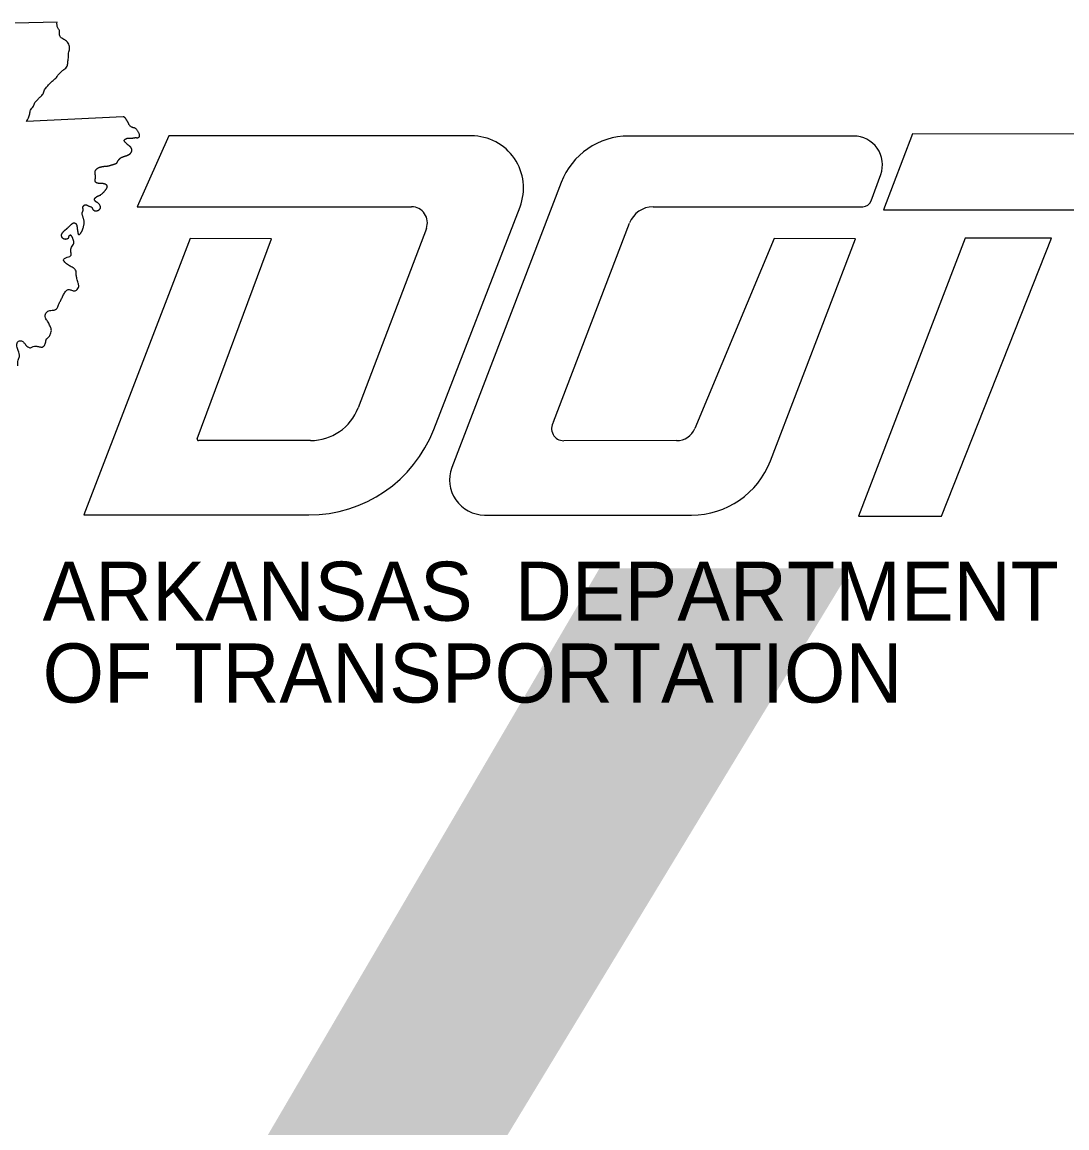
# Model space of a CAD drawing. Extents: x 1373878 to 1386598, y 1168333 to 1170533.
# Drawn here: x 1375442.6 to 1375493.8, y 1170196.3 to 1170250.5 of the extents above; entities that cross this region are included whole.
import ezdxf

# ---------------------------------------------------------------- set-up
doc = ezdxf.new("R2010")
doc.units = 0
doc.layers.add('1', color=7, linetype='Continuous')
doc.layers.add('R_Draft', color=7, linetype='Continuous')

msp = doc.modelspace()

# ---------------------------------------------------------------- linework, layer by layer
at = {"layer": '1'}
for p, q in [((1375447.561, 1170245.888), (1375442.814, 1170245.65)), ((1375449.8, 1170244.947), (1375448.241, 1170241.475)), ((1375464.634, 1170244.953), (1375449.8, 1170244.947)), ((1375483.381, 1170244.945), (1375472.342, 1170244.942)), ((1375486.266, 1170245.051), (1375484.847, 1170241.332)), ((1375503.446, 1170245.021), (1375486.266, 1170245.051)), ((1375484.236, 1170241.763), (1375484.706, 1170243.053)), ((1375469.04, 1170242.671), (1375463.68, 1170228.688)), ((1375448.241, 1170241.475), (1375461.698, 1170241.474)), ((1375462.79, 1170230.561), (1375467.02, 1170241.472)), ((1375473.546, 1170241.473), (1375483.827, 1170241.477)), ((1375484.847, 1170241.332), (1375501.324, 1170241.332)), ((1375468.667, 1170230.931), (1375472.394, 1170240.68)), ((1375462.428, 1170240.415), (1375459.082, 1170231.62)), ((1375454.839, 1170239.912), (1375450.847, 1170239.914)), ((1375451.196, 1170230.092), (1375454.839, 1170239.912)), ((1375479.485, 1170239.917), (1375475.598, 1170230.611)), ((1375479.303, 1170229.025), (1375483.476, 1170239.905)), ((1375483.476, 1170239.905), (1375479.485, 1170239.917)), ((1375488.854, 1170239.937), (1375483.624, 1170226.301)), ((1375487.68, 1170226.301), (1375493.076, 1170239.937)), ((1375493.076, 1170239.937), (1375488.854, 1170239.937)), ((1375456.751, 1170230.014), (1375451.251, 1170230.013)), ((1375474.7, 1170230.012), (1375469.166, 1170230.006)), ((1375465.277, 1170226.364), (1375475.427, 1170226.361)), ((1375483.624, 1170226.301), (1375487.68, 1170226.301))]:
    msp.add_line(p, q, dxfattribs=at)
for points in [[(1375444.317, 1170250.528), (1375439.463, 1170250.415), (1375428.999, 1170250.255), (1375420.123, 1170250.237), (1375410.017, 1170250.244)], [(1375450.847, 1170239.914), (1375445.637, 1170226.376), (1375456.659, 1170226.366)]]:
    msp.add_lwpolyline(points, dxfattribs=at)
for centre, radius, start, end in [((1375464.635, 1170242.396), 2.557, 338.81, 90.0244), ((1375472.343, 1170241.404), 3.538, 90.0159, 159.0252), ((1375483.381, 1170243.535), 1.41, 339.9797, 90.0159), ((1375483.827, 1170241.912), 0.435, 270.0183, 339.9797), ((1375461.698, 1170240.693), 0.781, 339.1692, 89.9954), ((1375473.547, 1170240.24), 1.234, 90.0183, 159.0781), ((1375456.751, 1170232.507), 2.494, 270.0081, 339.1692), ((1375469.164, 1170230.602), 0.596, 146.4856, 270.228), ((1375456.665, 1170232.935), 6.569, 269.9471, 338.81), ((1375474.699, 1170230.987), 0.975, 270.0618, 337.3322), ((1375451.251, 1170230.072), 0.0589, 159.6445, 270.0081), ((1375465.278, 1170228.076), 1.711, 159.0252, 269.9823), ((1375475.428, 1170230.511), 4.15, 269.9823, 339.0187)]:
    msp.add_arc(centre, radius, start, end, dxfattribs=at)
for points in [[(1375442.814, 1170245.65), (1375442.981, 1170246.03), (1375443.016, 1170246.218), (1375443.158, 1170246.407), (1375443.233, 1170246.581), (1375443.386, 1170246.748), (1375443.5, 1170246.872), (1375443.638, 1170247.011), (1375443.706, 1170247.203), (1375443.834, 1170247.377), (1375443.965, 1170247.515), (1375444.125, 1170247.672), (1375444.292, 1170247.821), (1375444.384, 1170247.963), (1375444.516, 1170248.094), (1375444.658, 1170248.205), (1375444.811, 1170248.361), (1375444.846, 1170248.556), (1375444.871, 1170248.77), (1375444.882, 1170249.011), (1375444.931, 1170249.228), (1375444.896, 1170249.441), (1375444.736, 1170249.626), (1375444.555, 1170249.736), (1375444.448, 1170249.85), (1375444.434, 1170250.113), (1375444.349, 1170250.255), (1375444.317, 1170250.528)], [(1375444.089, 1170236.404), (1375444.239, 1170236.433), (1375444.377, 1170236.621), (1375444.445, 1170236.781), (1375444.516, 1170236.93), (1375444.608, 1170237.108), (1375444.701, 1170237.278), (1375444.832, 1170237.406), (1375444.995, 1170237.396), (1375445.138, 1170237.349), (1375445.269, 1170237.389), (1375445.379, 1170237.573), (1375445.354, 1170237.733), (1375445.294, 1170237.954), (1375445.262, 1170238.121), (1375445.226, 1170238.373), (1375445.109, 1170238.483), (1375444.921, 1170238.586), (1375444.736, 1170238.728), (1375444.633, 1170238.874), (1375444.811, 1170239.002), (1375445.01, 1170239.108), (1375444.988, 1170239.304), (1375445.027, 1170239.496), (1375445.138, 1170239.691), (1375445.113, 1170239.869)], [(1375442.394, 1170233.672), (1375442.416, 1170233.963), (1375442.473, 1170234.134), (1375442.412, 1170234.422), (1375442.352, 1170234.635), (1375442.377, 1170234.841), (1375442.508, 1170234.908), (1375442.636, 1170234.866), (1375442.746, 1170234.752), (1375442.881, 1170234.606), (1375443.013, 1170234.56), (1375443.148, 1170234.631), (1375443.286, 1170234.642), (1375443.446, 1170234.613), (1375443.595, 1170234.599), (1375443.674, 1170234.649), (1375443.752, 1170234.798), (1375443.805, 1170234.997), (1375443.915, 1170235.093), (1375444.001, 1170235.25), (1375444.036, 1170235.459), (1375443.972, 1170235.63), (1375443.883, 1170235.822), (1375443.77, 1170235.981), (1375443.752, 1170236.212), (1375443.869, 1170236.351), (1375444.072, 1170236.401), (1375444.089, 1170236.404)]]:
    msp.add_spline(points, degree=3, dxfattribs=at)
for points in [[(1375447.904, 1170244.833), (1375447.919, 1170244.831), (1375447.934, 1170244.83), (1375447.948, 1170244.833), (1375447.98, 1170244.838), (1375448.012, 1170244.843), (1375448.044, 1170244.848), (1375448.076, 1170244.854), (1375448.108, 1170244.859), (1375448.14, 1170244.865), (1375448.147, 1170244.866), (1375448.155, 1170244.866), (1375448.162, 1170244.866), (1375448.17, 1170244.866), (1375448.177, 1170244.866), (1375448.184, 1170244.865), (1375448.199, 1170244.864), (1375448.214, 1170244.863), (1375448.229, 1170244.861), (1375448.244, 1170244.86), (1375448.259, 1170244.861), (1375448.273, 1170244.863), (1375448.289, 1170244.865), (1375448.304, 1170244.871), (1375448.318, 1170244.879), (1375448.321, 1170244.881), (1375448.323, 1170244.882), (1375448.326, 1170244.885), (1375448.329, 1170244.887), (1375448.331, 1170244.889), (1375448.333, 1170244.891), (1375448.338, 1170244.896), (1375448.342, 1170244.9), (1375448.346, 1170244.906), (1375448.353, 1170244.917), (1375448.358, 1170244.928), (1375448.361, 1170244.941), (1375448.365, 1170244.954), (1375448.366, 1170244.966), (1375448.366, 1170244.979), (1375448.365, 1170244.99), (1375448.364, 1170245.002), (1375448.36, 1170245.014), (1375448.342, 1170245.072), (1375448.315, 1170245.122), (1375448.282, 1170245.174), (1375448.248, 1170245.228), (1375448.212, 1170245.276), (1375448.161, 1170245.316), (1375448.15, 1170245.325), (1375448.138, 1170245.331), (1375448.124, 1170245.335), (1375448.11, 1170245.339), (1375448.096, 1170245.342), (1375448.083, 1170245.345), (1375448.069, 1170245.348), (1375448.054, 1170245.35), (1375448.041, 1170245.354), (1375448.027, 1170245.357), (1375448.014, 1170245.362), (1375448.001, 1170245.369), (1375447.951, 1170245.397), (1375447.906, 1170245.431), (1375447.87, 1170245.476), (1375447.859, 1170245.49), (1375447.849, 1170245.505), (1375447.841, 1170245.521), (1375447.833, 1170245.537), (1375447.826, 1170245.553), (1375447.819, 1170245.569), (1375447.811, 1170245.585), (1375447.805, 1170245.601), (1375447.797, 1170245.617), (1375447.789, 1170245.633), (1375447.78, 1170245.649), (1375447.771, 1170245.664), (1375447.763, 1170245.675), (1375447.756, 1170245.687), (1375447.749, 1170245.698), (1375447.742, 1170245.71), (1375447.735, 1170245.722), (1375447.727, 1170245.734), (1375447.713, 1170245.757), (1375447.697, 1170245.78), (1375447.682, 1170245.803), (1375447.667, 1170245.825), (1375447.65, 1170245.843), (1375447.628, 1170245.859), (1375447.608, 1170245.874), (1375447.585, 1170245.885), (1375447.561, 1170245.888)], [(1375447.341, 1170243.778), (1375447.344, 1170243.781), (1375447.347, 1170243.785), (1375447.351, 1170243.788), (1375447.364, 1170243.803), (1375447.377, 1170243.817), (1375447.39, 1170243.83), (1375447.404, 1170243.844), (1375447.418, 1170243.857), (1375447.434, 1170243.868), (1375447.449, 1170243.88), (1375447.465, 1170243.89), (1375447.483, 1170243.898), (1375447.499, 1170243.906), (1375447.515, 1170243.913), (1375447.532, 1170243.918), (1375447.548, 1170243.924), (1375447.565, 1170243.93), (1375447.582, 1170243.935), (1375447.599, 1170243.941), (1375447.615, 1170243.946), (1375447.632, 1170243.951), (1375447.649, 1170243.957), (1375447.665, 1170243.963), (1375447.682, 1170243.969), (1375447.715, 1170243.981), (1375447.748, 1170243.994), (1375447.78, 1170244.008), (1375447.814, 1170244.021), (1375447.846, 1170244.039), (1375447.877, 1170244.058), (1375447.892, 1170244.067), (1375447.904, 1170244.079), (1375447.916, 1170244.091), (1375447.928, 1170244.104), (1375447.937, 1170244.117), (1375447.946, 1170244.132), (1375447.962, 1170244.161), (1375447.974, 1170244.19), (1375447.98, 1170244.221), (1375447.983, 1170244.236), (1375447.984, 1170244.25), (1375447.983, 1170244.264), (1375447.981, 1170244.279), (1375447.979, 1170244.294), (1375447.975, 1170244.309), (1375447.97, 1170244.324), (1375447.965, 1170244.339), (1375447.957, 1170244.353), (1375447.949, 1170244.367), (1375447.941, 1170244.38), (1375447.93, 1170244.392), (1375447.917, 1170244.408), (1375447.903, 1170244.422), (1375447.887, 1170244.435), (1375447.872, 1170244.448), (1375447.856, 1170244.46), (1375447.841, 1170244.472), (1375447.825, 1170244.484), (1375447.809, 1170244.496), (1375447.794, 1170244.508), (1375447.779, 1170244.521), (1375447.764, 1170244.535), (1375447.749, 1170244.548), (1375447.72, 1170244.575), (1375447.692, 1170244.603), (1375447.664, 1170244.631), (1375447.651, 1170244.644), (1375447.64, 1170244.659), (1375447.629, 1170244.674), (1375447.62, 1170244.687), (1375447.614, 1170244.7), (1375447.611, 1170244.715), (1375447.61, 1170244.718), (1375447.61, 1170244.722), (1375447.61, 1170244.725), (1375447.61, 1170244.728), (1375447.611, 1170244.731), (1375447.612, 1170244.734), (1375447.614, 1170244.741), (1375447.617, 1170244.747), (1375447.621, 1170244.752), (1375447.632, 1170244.766), (1375447.644, 1170244.777), (1375447.659, 1170244.787), (1375447.676, 1170244.798), (1375447.692, 1170244.808), (1375447.711, 1170244.817), (1375447.728, 1170244.826), (1375447.745, 1170244.833), (1375447.763, 1170244.84), (1375447.771, 1170244.842), (1375447.779, 1170244.844), (1375447.787, 1170244.845), (1375447.794, 1170244.847), (1375447.802, 1170244.847), (1375447.81, 1170244.847), (1375447.825, 1170244.845), (1375447.841, 1170244.843), (1375447.856, 1170244.841), (1375447.872, 1170244.839), (1375447.887, 1170244.835), (1375447.902, 1170244.833), (1375447.903, 1170244.833), (1375447.903, 1170244.833), (1375447.904, 1170244.833)], [(1375446.185, 1170242.779), (1375446.186, 1170242.792), (1375446.187, 1170242.805), (1375446.189, 1170242.818), (1375446.193, 1170242.838), (1375446.199, 1170242.858), (1375446.202, 1170242.878), (1375446.205, 1170242.898), (1375446.208, 1170242.919), (1375446.207, 1170242.939), (1375446.206, 1170242.958), (1375446.204, 1170242.977), (1375446.201, 1170242.996), (1375446.198, 1170243.016), (1375446.195, 1170243.035), (1375446.193, 1170243.054), (1375446.19, 1170243.073), (1375446.187, 1170243.093), (1375446.185, 1170243.112), (1375446.183, 1170243.131), (1375446.182, 1170243.15), (1375446.182, 1170243.17), (1375446.182, 1170243.185), (1375446.185, 1170243.199), (1375446.188, 1170243.214), (1375446.191, 1170243.229), (1375446.196, 1170243.243), (1375446.204, 1170243.257), (1375446.221, 1170243.286), (1375446.24, 1170243.311), (1375446.264, 1170243.333), (1375446.271, 1170243.34), (1375446.279, 1170243.347), (1375446.287, 1170243.353), (1375446.295, 1170243.359), (1375446.303, 1170243.364), (1375446.311, 1170243.37), (1375446.327, 1170243.38), (1375446.343, 1170243.389), (1375446.36, 1170243.396), (1375446.376, 1170243.404), (1375446.393, 1170243.41), (1375446.41, 1170243.415), (1375446.428, 1170243.42), (1375446.445, 1170243.425), (1375446.463, 1170243.429), (1375446.495, 1170243.436), (1375446.528, 1170243.443), (1375446.56, 1170243.449), (1375446.593, 1170243.455), (1375446.626, 1170243.46), (1375446.658, 1170243.465), (1375446.673, 1170243.466), (1375446.688, 1170243.468), (1375446.703, 1170243.469), (1375446.718, 1170243.47), (1375446.733, 1170243.471), (1375446.747, 1170243.472), (1375446.762, 1170243.473), (1375446.777, 1170243.474), (1375446.792, 1170243.475), (1375446.807, 1170243.477), (1375446.821, 1170243.479), (1375446.836, 1170243.482), (1375446.87, 1170243.49), (1375446.903, 1170243.499), (1375446.936, 1170243.509), (1375446.969, 1170243.519), (1375447.002, 1170243.529), (1375447.035, 1170243.539), (1375447.067, 1170243.549), (1375447.1, 1170243.558), (1375447.132, 1170243.568), (1375447.164, 1170243.578), (1375447.196, 1170243.589), (1375447.227, 1170243.603), (1375447.239, 1170243.609), (1375447.25, 1170243.618), (1375447.257, 1170243.629), (1375447.264, 1170243.642), (1375447.269, 1170243.654), (1375447.275, 1170243.667), (1375447.28, 1170243.681), (1375447.284, 1170243.695), (1375447.29, 1170243.709), (1375447.296, 1170243.722), (1375447.303, 1170243.734), (1375447.312, 1170243.745), (1375447.322, 1170243.756), (1375447.331, 1170243.767), (1375447.341, 1170243.778)], [(1375446.217, 1170241.725), (1375446.214, 1170241.728), (1375446.21, 1170241.731), (1375446.207, 1170241.734), (1375446.187, 1170241.753), (1375446.173, 1170241.775), (1375446.161, 1170241.799), (1375446.151, 1170241.82), (1375446.147, 1170241.846), (1375446.157, 1170241.866), (1375446.165, 1170241.879), (1375446.174, 1170241.891), (1375446.185, 1170241.903), (1375446.197, 1170241.915), (1375446.208, 1170241.927), (1375446.221, 1170241.937), (1375446.248, 1170241.96), (1375446.276, 1170241.98), (1375446.307, 1170241.997), (1375446.319, 1170242.004), (1375446.332, 1170242.011), (1375446.346, 1170242.016), (1375446.359, 1170242.02), (1375446.373, 1170242.025), (1375446.386, 1170242.03), (1375446.4, 1170242.034), (1375446.413, 1170242.039), (1375446.426, 1170242.044), (1375446.439, 1170242.049), (1375446.451, 1170242.056), (1375446.463, 1170242.065), (1375446.519, 1170242.106), (1375446.569, 1170242.153), (1375446.616, 1170242.203), (1375446.628, 1170242.217), (1375446.64, 1170242.23), (1375446.652, 1170242.244), (1375446.663, 1170242.258), (1375446.674, 1170242.272), (1375446.685, 1170242.286), (1375446.707, 1170242.314), (1375446.727, 1170242.344), (1375446.747, 1170242.374), (1375446.761, 1170242.395), (1375446.771, 1170242.419), (1375446.779, 1170242.443), (1375446.783, 1170242.455), (1375446.784, 1170242.468), (1375446.782, 1170242.48), (1375446.78, 1170242.491), (1375446.776, 1170242.502), (1375446.769, 1170242.512), (1375446.763, 1170242.52), (1375446.757, 1170242.526), (1375446.751, 1170242.532), (1375446.744, 1170242.538), (1375446.738, 1170242.544), (1375446.731, 1170242.549), (1375446.718, 1170242.559), (1375446.703, 1170242.568), (1375446.688, 1170242.576), (1375446.657, 1170242.591), (1375446.625, 1170242.602), (1375446.591, 1170242.608), (1375446.576, 1170242.611), (1375446.561, 1170242.613), (1375446.546, 1170242.613), (1375446.531, 1170242.613), (1375446.515, 1170242.613), (1375446.5, 1170242.613), (1375446.485, 1170242.612), (1375446.47, 1170242.612), (1375446.455, 1170242.612), (1375446.44, 1170242.612), (1375446.425, 1170242.614), (1375446.41, 1170242.615), (1375446.391, 1170242.618), (1375446.372, 1170242.62), (1375446.353, 1170242.623), (1375446.333, 1170242.626), (1375446.314, 1170242.63), (1375446.295, 1170242.634), (1375446.277, 1170242.637), (1375446.26, 1170242.645), (1375446.244, 1170242.655), (1375446.227, 1170242.666), (1375446.214, 1170242.68), (1375446.204, 1170242.697), (1375446.201, 1170242.702), (1375446.198, 1170242.707), (1375446.196, 1170242.712), (1375446.194, 1170242.717), (1375446.192, 1170242.722), (1375446.19, 1170242.727), (1375446.187, 1170242.737), (1375446.185, 1170242.747), (1375446.185, 1170242.757), (1375446.185, 1170242.764), (1375446.185, 1170242.772), (1375446.185, 1170242.779)], [(1375445.546, 1170241.148), (1375445.547, 1170241.155), (1375445.548, 1170241.162), (1375445.549, 1170241.168), (1375445.553, 1170241.185), (1375445.558, 1170241.201), (1375445.565, 1170241.217), (1375445.571, 1170241.234), (1375445.579, 1170241.249), (1375445.585, 1170241.266), (1375445.591, 1170241.282), (1375445.596, 1170241.298), (1375445.599, 1170241.315), (1375445.601, 1170241.322), (1375445.601, 1170241.329), (1375445.6, 1170241.337), (1375445.6, 1170241.344), (1375445.599, 1170241.351), (1375445.598, 1170241.359), (1375445.595, 1170241.374), (1375445.591, 1170241.388), (1375445.588, 1170241.403), (1375445.585, 1170241.418), (1375445.583, 1170241.433), (1375445.584, 1170241.448), (1375445.584, 1170241.464), (1375445.591, 1170241.479), (1375445.599, 1170241.493), (1375445.604, 1170241.499), (1375445.609, 1170241.505), (1375445.614, 1170241.512), (1375445.619, 1170241.518), (1375445.624, 1170241.524), (1375445.629, 1170241.53), (1375445.639, 1170241.541), (1375445.65, 1170241.55), (1375445.663, 1170241.56), (1375445.673, 1170241.568), (1375445.686, 1170241.573), (1375445.698, 1170241.576), (1375445.71, 1170241.579), (1375445.723, 1170241.579), (1375445.735, 1170241.574), (1375445.775, 1170241.558), (1375445.815, 1170241.538), (1375445.855, 1170241.521), (1375445.9, 1170241.502), (1375445.946, 1170241.487), (1375445.99, 1170241.468), (1375446.005, 1170241.461), (1375446.018, 1170241.451), (1375446.026, 1170241.438), (1375446.035, 1170241.423), (1375446.042, 1170241.409), (1375446.05, 1170241.394), (1375446.058, 1170241.379), (1375446.065, 1170241.363), (1375446.074, 1170241.348), (1375446.082, 1170241.333), (1375446.093, 1170241.322), (1375446.108, 1170241.311), (1375446.133, 1170241.293), (1375446.161, 1170241.284), (1375446.19, 1170241.279), (1375446.218, 1170241.274), (1375446.247, 1170241.273), (1375446.275, 1170241.279), (1375446.302, 1170241.286), (1375446.329, 1170241.295), (1375446.354, 1170241.31), (1375446.367, 1170241.318), (1375446.379, 1170241.327), (1375446.391, 1170241.337), (1375446.397, 1170241.342), (1375446.402, 1170241.347), (1375446.408, 1170241.353), (1375446.414, 1170241.359), (1375446.419, 1170241.365), (1375446.424, 1170241.372), (1375446.45, 1170241.408), (1375446.45, 1170241.463), (1375446.435, 1170241.503), (1375446.414, 1170241.555), (1375446.384, 1170241.604), (1375446.342, 1170241.645), (1375446.332, 1170241.655), (1375446.322, 1170241.664), (1375446.31, 1170241.671), (1375446.299, 1170241.677), (1375446.287, 1170241.684), (1375446.275, 1170241.69), (1375446.263, 1170241.696), (1375446.251, 1170241.703), (1375446.24, 1170241.709), (1375446.231, 1170241.713), (1375446.224, 1170241.719), (1375446.217, 1170241.725)], [(1375445.15, 1170240.69), (1375445.153, 1170240.69), (1375445.157, 1170240.69), (1375445.16, 1170240.69), (1375445.178, 1170240.688), (1375445.196, 1170240.68), (1375445.212, 1170240.668), (1375445.223, 1170240.66), (1375445.231, 1170240.652), (1375445.239, 1170240.643), (1375445.247, 1170240.634), (1375445.254, 1170240.626), (1375445.261, 1170240.616), (1375445.267, 1170240.607), (1375445.273, 1170240.597), (1375445.277, 1170240.587), (1375445.281, 1170240.576), (1375445.285, 1170240.566), (1375445.287, 1170240.554), (1375445.29, 1170240.539), (1375445.293, 1170240.523), (1375445.294, 1170240.507), (1375445.296, 1170240.491), (1375445.298, 1170240.475), (1375445.3, 1170240.459), (1375445.304, 1170240.427), (1375445.308, 1170240.395), (1375445.312, 1170240.363), (1375445.317, 1170240.322), (1375445.325, 1170240.282), (1375445.332, 1170240.242), (1375445.339, 1170240.202), (1375445.349, 1170240.164), (1375445.361, 1170240.125), (1375445.363, 1170240.12), (1375445.365, 1170240.116), (1375445.37, 1170240.113), (1375445.374, 1170240.11), (1375445.379, 1170240.11), (1375445.383, 1170240.111), (1375445.396, 1170240.113), (1375445.408, 1170240.118), (1375445.419, 1170240.126), (1375445.446, 1170240.146), (1375445.469, 1170240.166), (1375445.486, 1170240.192), (1375445.497, 1170240.21), (1375445.508, 1170240.227), (1375445.518, 1170240.246), (1375445.528, 1170240.263), (1375445.538, 1170240.281), (1375445.547, 1170240.299), (1375445.556, 1170240.317), (1375445.564, 1170240.336), (1375445.572, 1170240.355), (1375445.58, 1170240.374), (1375445.586, 1170240.393), (1375445.592, 1170240.412), (1375445.615, 1170240.484), (1375445.63, 1170240.556), (1375445.642, 1170240.629), (1375445.651, 1170240.678), (1375445.658, 1170240.73), (1375445.646, 1170240.778), (1375445.629, 1170240.844), (1375445.611, 1170240.909), (1375445.592, 1170240.974), (1375445.579, 1170241.022), (1375445.563, 1170241.071), (1375445.55, 1170241.119), (1375445.547, 1170241.129), (1375445.546, 1170241.138), (1375445.546, 1170241.148)], [(1375445.113, 1170239.869), (1375445.1, 1170239.904), (1375445.088, 1170239.939), (1375445.07, 1170239.973), (1375445.062, 1170239.989), (1375445.053, 1170240.005), (1375445.043, 1170240.02), (1375445.038, 1170240.028), (1375445.032, 1170240.035), (1375445.027, 1170240.043), (1375445.021, 1170240.05), (1375445.016, 1170240.057), (1375445.01, 1170240.064), (1375445.004, 1170240.071), (1375444.995, 1170240.075), (1375444.987, 1170240.076), (1375444.977, 1170240.078), (1375444.967, 1170240.077), (1375444.957, 1170240.074), (1375444.947, 1170240.071), (1375444.937, 1170240.068), (1375444.927, 1170240.063), (1375444.918, 1170240.058), (1375444.91, 1170240.054), (1375444.903, 1170240.046), (1375444.895, 1170240.038), (1375444.89, 1170240.028), (1375444.887, 1170240.018), (1375444.885, 1170240.006), (1375444.883, 1170239.994), (1375444.881, 1170239.982), (1375444.878, 1170239.97), (1375444.876, 1170239.958), (1375444.872, 1170239.946), (1375444.868, 1170239.935), (1375444.86, 1170239.926), (1375444.85, 1170239.918), (1375444.841, 1170239.912), (1375444.832, 1170239.907), (1375444.823, 1170239.903), (1375444.814, 1170239.898), (1375444.806, 1170239.894), (1375444.797, 1170239.89), (1375444.788, 1170239.887), (1375444.779, 1170239.884), (1375444.77, 1170239.882), (1375444.761, 1170239.881), (1375444.752, 1170239.88), (1375444.743, 1170239.879), (1375444.732, 1170239.879), (1375444.72, 1170239.88), (1375444.709, 1170239.881), (1375444.697, 1170239.882), (1375444.685, 1170239.885), (1375444.674, 1170239.888), (1375444.662, 1170239.892), (1375444.65, 1170239.897), (1375444.639, 1170239.904), (1375444.627, 1170239.911), (1375444.615, 1170239.919), (1375444.605, 1170239.929), (1375444.601, 1170239.933), (1375444.597, 1170239.936), (1375444.593, 1170239.94), (1375444.589, 1170239.944), (1375444.586, 1170239.948), (1375444.583, 1170239.952), (1375444.576, 1170239.96), (1375444.57, 1170239.968), (1375444.565, 1170239.976), (1375444.554, 1170239.992), (1375444.547, 1170240.009), (1375444.541, 1170240.027), (1375444.535, 1170240.044), (1375444.533, 1170240.061), (1375444.534, 1170240.078), (1375444.535, 1170240.093), (1375444.538, 1170240.109), (1375444.544, 1170240.125), (1375444.55, 1170240.139), (1375444.557, 1170240.153), (1375444.565, 1170240.166), (1375444.572, 1170240.181), (1375444.58, 1170240.195), (1375444.59, 1170240.208), (1375444.609, 1170240.236), (1375444.63, 1170240.262), (1375444.654, 1170240.284), (1375444.669, 1170240.298), (1375444.684, 1170240.311), (1375444.7, 1170240.324), (1375444.715, 1170240.336), (1375444.73, 1170240.349), (1375444.746, 1170240.361), (1375444.761, 1170240.374), (1375444.776, 1170240.386), (1375444.791, 1170240.398), (1375444.807, 1170240.411), (1375444.821, 1170240.424), (1375444.836, 1170240.437), (1375444.86, 1170240.461), (1375444.884, 1170240.484), (1375444.908, 1170240.508), (1375444.933, 1170240.532), (1375444.957, 1170240.556), (1375444.981, 1170240.579), (1375445.001, 1170240.598), (1375445.022, 1170240.616), (1375445.043, 1170240.632), (1375445.054, 1170240.64), (1375445.065, 1170240.648), (1375445.076, 1170240.656), (1375445.087, 1170240.664), (1375445.098, 1170240.672), (1375445.109, 1170240.679), (1375445.121, 1170240.686), (1375445.136, 1170240.69), (1375445.15, 1170240.69)]]:
    msp.add_open_spline(points, degree=3, dxfattribs=at)

# ---------------------------------------------------------------- texts
for s, p in [('ARKANSAS', (1375443.609, 1170221.181)), ('DEPARTMENT', (1375466.769, 1170221.181)), ('OF TRANSPORTATION', (1375443.609, 1170217.172))]:
    msp.add_text(s, height=2.8953, dxfattribs=at).set_placement(p)
at = {"layer": 'R_Draft'}
msp.add_text('I-57 HWY. 5 INTCHNG.', height=90, dxfattribs=at).set_placement((1374964.309, 1170133.758))

doc.saveas('drawing.dxf')
